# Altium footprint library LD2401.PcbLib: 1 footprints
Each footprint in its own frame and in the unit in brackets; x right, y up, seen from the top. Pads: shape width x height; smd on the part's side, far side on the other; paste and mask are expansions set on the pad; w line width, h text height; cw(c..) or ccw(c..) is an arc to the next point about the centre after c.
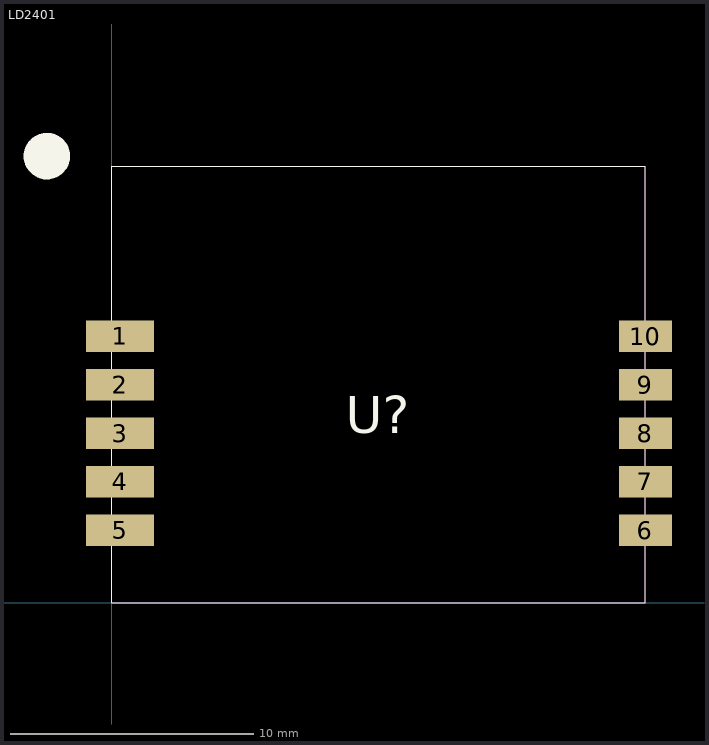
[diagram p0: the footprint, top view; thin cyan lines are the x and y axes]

## LD2401 [mm]
height 0.457
pads (10):
  rect 2.8x1.3 / inner rect 0x0 / far side rect 0x0 all layers, no hole: 1(0.35,11)
  rect 2.8x1.3 smd: 2(0.35,9) 3(0.35,7) 4(0.35,5) 5(0.35,3)
  rect 2.2x1.3 smd: 6(22,3) 7(22,5) 8(22,7) 9(22,9) 10(22,11)
Top Overlay:
  circle w1: c-2.667,18.415 r0.458
  lines w0.025: 0,0 22,0 22,18 0,18 0,0
  text "U?" at 9.652,6.985 h1.52
Keep-Out Layer:
  lines w0.025: 0,0 22,0 22,18 0,18 0,0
